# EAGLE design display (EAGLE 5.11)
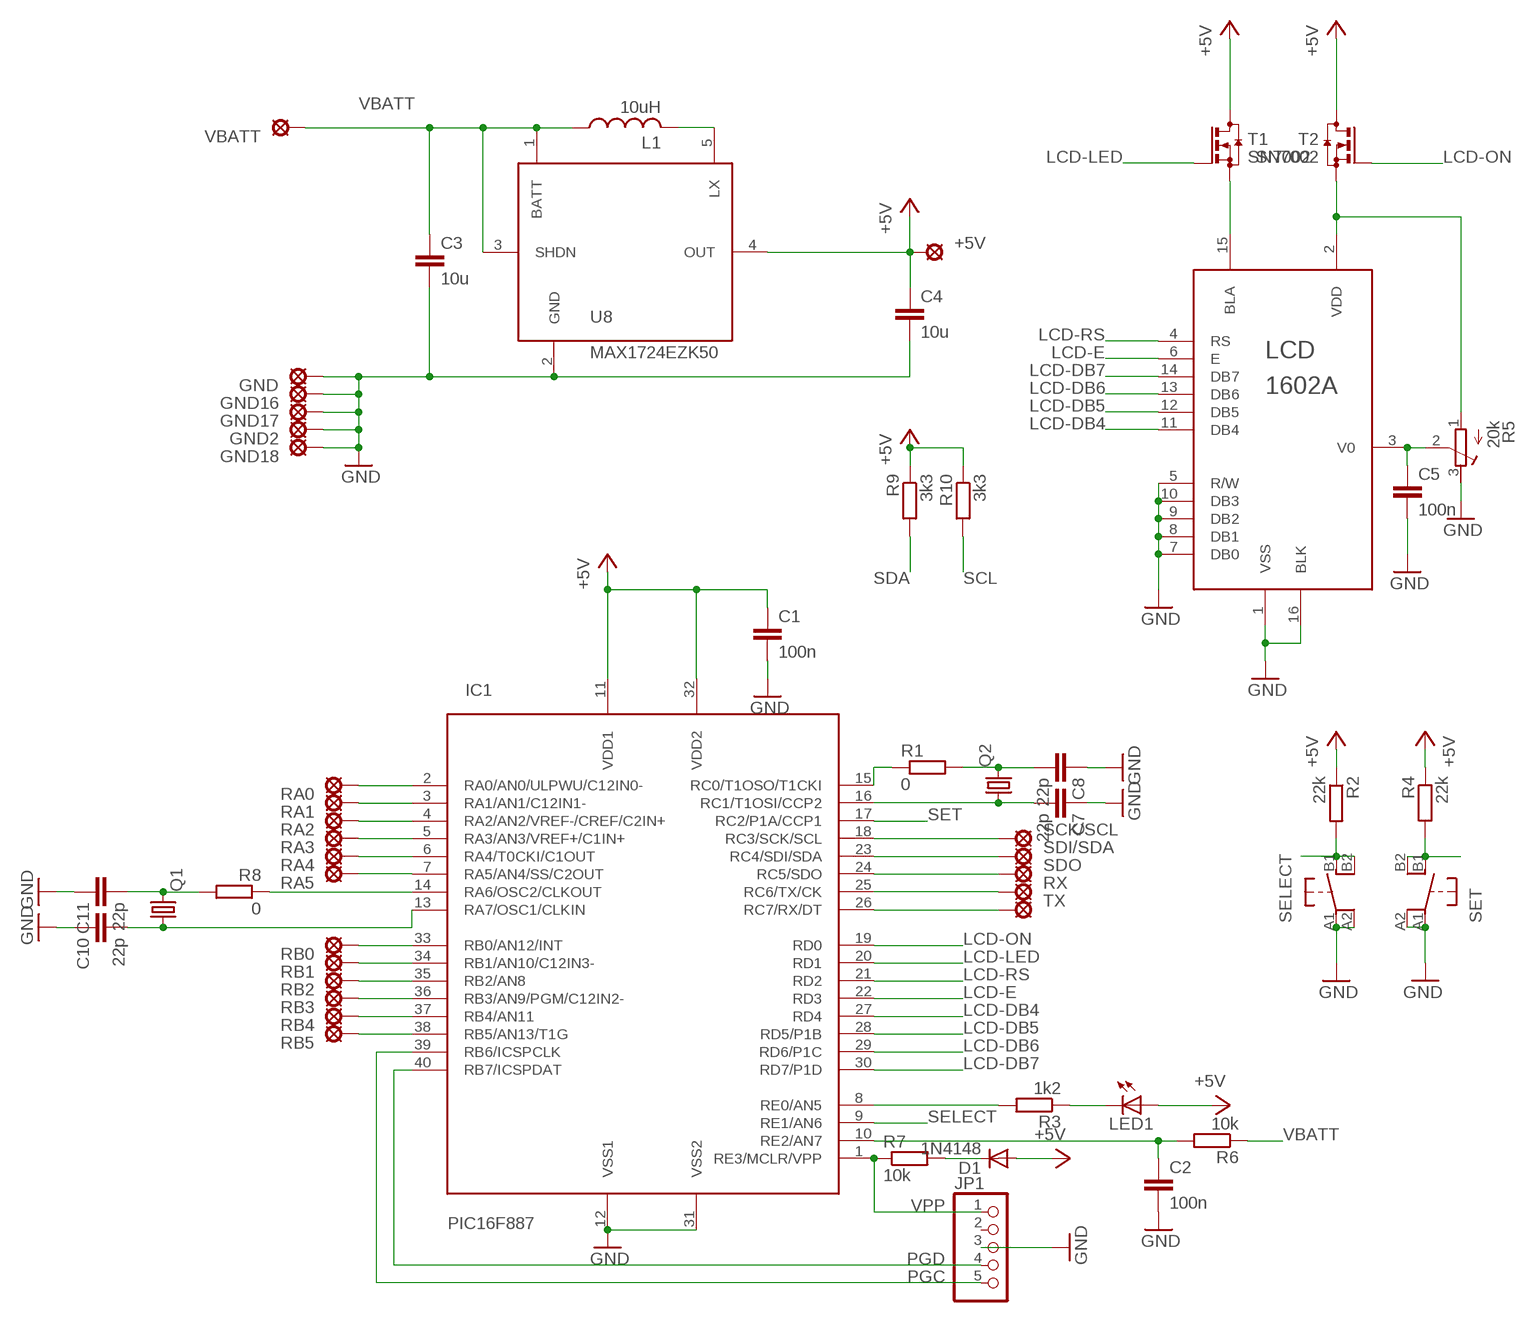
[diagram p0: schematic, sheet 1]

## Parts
+5V  LSP10  [LSP10]
C1  100n  C-EUC0805  [C0805]
C2  100n  C-EUC0805  [C0805]
C3  10u  C-EUC1210  [C1210]
C4  10u  C-EUC1210  [C1210]
C5  100n  C-EUC0805  [C0805]
C7  22p  C-EUC0805  [C0805]
C8  22p  C-EUC0805  [C0805]
C10  22p  C-EUC0805  [C0805]
C11  22p  C-EUC0805  [C0805]
D1  1N4148  1N4148DO35-7  [DO35-7]
GND  LSP10  [LSP10]
GND2  LSP10  [LSP10]
GND16  LSP10  [LSP10]
GND17  LSP10  [LSP10]
GND18  LSP10  [LSP10]
IC1  PIC16F887  [DIL40]
JP1  PINHD-1X5  [1X05]
L1  10uH  COIL-BOURNS  [COIL_BURNS]
LCD  1602A  [1602A]
LED1  LED5MM  [LED5MM]
Q1  CRYSTALSM49  [SM49]
Q2  CRYSTALSM49  [SM49]
R1  0  R-EU_M0805  [M0805]
R2  22k  R-EU_M0805  [M0805]
R3  1k2  R-EU_M0805  [M0805]
R4  22k  R-EU_M0805  [M0805]
R5  20k  R-TRIMM3339P  [RTRIM3339P]
R6  10k  R-EU_M0805  [M0805]
R7  10k  R-EU_M0805  [M0805]
R8  0  R-EU_M0805  [M0805]
R9  3k3  R-EU_M0805  [M0805]
R10  3k3  R-EU_M0805  [M0805]
RA0  LSP10  [LSP10]
RA1  LSP10  [LSP10]
RA2  LSP10  [LSP10]
RA3  LSP10  [LSP10]
RA4  LSP10  [LSP10]
RA5  LSP10  [LSP10]
RB0  LSP10  [LSP10]
RB1  LSP10  [LSP10]
RB2  LSP10  [LSP10]
RB3  LSP10  [LSP10]
RB4  LSP10  [LSP10]
RB5  LSP10  [LSP10]
RX  LSP10  [LSP10]
SCK/SCL  LSP10  [LSP10]
SDI/SDA  LSP10  [LSP10]
SDO  LSP10  [LSP10]
SELECT  PUSHBUTTON  [PUSHBUTTON]
SET  PUSHBUTTON  [PUSHBUTTON]
T1  SN7002  BSS123  [SOT23]
T2  SN7002  BSS123  [SOT23]
TX  LSP10  [LSP10]
U8  MAX1724EZK50  MAX1724  [SOT23-5L]
VBATT  LSP10  [LSP10]

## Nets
+5V: +5V.MP C1.1 C4.1 D1.A IC1.11(VDD1) IC1.32(VDD2) LED1.A R2.1 R4.1 R9.1 R10.1 T1.3(D) T2.3(D) U8.4(OUT)
GND: C1.2 C2.2 C3.2 C4.2 C5.2 C7.1 C8.1 C10.1 C11.1 GND2.MP GND16.MP GND17.MP GND18.MP GND.MP IC1.12(VSS1) IC1.31(VSS2) JP1.3 LCD.1(VSS) LCD.5(R/W) LCD.7(DB0) LCD.8(DB1) LCD.9(DB2) LCD.10(DB3) LCD.16(BLK) R5.3(A) SELECT.A1(P) SELECT.A2(P1) SET.A1(P) SET.A2(P1) U8.2(GND)
LCD-DB4: IC1.27(RD4) LCD.11(DB4)
LCD-DB5: IC1.28(RD5/P1B) LCD.12(DB5)
LCD-DB6: IC1.29(RD6/P1C) LCD.13(DB6)
LCD-DB7: IC1.30(RD7/P1D) LCD.14(DB7)
LCD-E: IC1.22(RD3) LCD.6(E)
LCD-LED: IC1.20(RD1) T1.1(G)
LCD-ON: IC1.19(RD0) T2.1(G)
LCD-RS: IC1.21(RD2) LCD.4(RS)
N$1: LCD.15(BLA) T1.2(S)
N$2: LCD.2(VDD) R5.1(E) T2.2(S)
N$3: C7.2 IC1.16(RC1/T1OSI/CCP2) Q2.1
N$4: C8.2 Q2.2 R1.2
N$5: C5.1 LCD.3(V0) R5.2(S)
N$6: LED1.K(C) R3.1
N$7: IC1.15(RC0/T1OSO/T1CKI) R1.1
N$8: C2.1 IC1.10(RE2/AN7) R6.2
N$9: D1.C R7.2
N$10: IC1.7(RA5/AN4/SS/C2OUT) RA5.MP
N$11: C10.2 IC1.13(RA7/OSC1/CLKIN) Q1.1
N$12: L1.P$2 U8.5(LX)
N$13: IC1.8(RE0/AN5) R3.2
N$16: IC1.24(RC5/SDO) SDO.MP
N$17: C11.2 Q1.2 R8.2
N$18: IC1.14(RA6/OSC2/CLKOUT) R8.1
N$19: IC1.25(RC6/TX/CK) RX.MP
N$20: IC1.26(RC7/RX/DT) TX.MP
N$21: IC1.2(RA0/AN0/ULPWU/C12IN0-) RA0.MP
N$22: IC1.3(RA1/AN1/C12IN1-) RA1.MP
N$23: IC1.4(RA2/AN2/VREF-/CREF/C2IN+) RA2.MP
N$24: IC1.5(RA3/AN3/VREF+/C1IN+) RA3.MP
N$25: IC1.6(RA4/T0CKI/C1OUT) RA4.MP
N$26: IC1.33(RB0/AN12/INT) RB0.MP
N$27: IC1.34(RB1/AN10/C12IN3-) RB1.MP
N$28: IC1.35(RB2/AN8) RB2.MP
N$29: IC1.36(RB3/AN9/PGM/C12IN2-) RB3.MP
N$30: IC1.37(RB4/AN11) RB4.MP
N$31: IC1.38(RB5/AN13/T1G) RB5.MP
PGC: IC1.39(RB6/ICSPCLK) JP1.5
PGD: IC1.40(RB7/ICSPDAT) JP1.4
SCL: IC1.18(RC3/SCK/SCL) R10.2 SCK/SCL.MP
SDA: IC1.23(RC4/SDI/SDA) R9.2 SDI/SDA.MP
SELECT: IC1.9(RE1/AN6) R2.2 SELECT.B1(S) SELECT.B2(S1)
SET: IC1.17(RC2/P1A/CCP1) R4.2 SET.B1(S) SET.B2(S1)
VBATT: C3.1 L1.P$1 R6.1 U8.1(BATT) U8.3(SHDN) VBATT.MP
VPP: IC1.1(RE3/MCLR/VPP) JP1.1 R7.1
Unconnected: JP1.2

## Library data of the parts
+5V GND GND2 GND16-GND18 RA0 RA1-RA5 RB0 RB1-RB5 RX SCK/SCL SDI/SDA SDO TX VBATT = solpad:LSP10: SOLDER PAD
C1-C5 C7 C8 C10 C11 = rcl:C-EU: CAPACITOR, European symbol
D1 = diode:1N4148: DIODE
IC1 = pic16f887:PIC16F887
JP1 = pinhead:PINHD-1X5: PIN HEADER
L1 = powersupply:COIL-BOURNS
LCD = 1602A:1602A
LED1 = led:LED: LED
Q1 Q2 = crystal:CRYSTAL: CRYSTAL; OC_FARNELL: unknown; OC_NEWARK: unknown
R1-R4 R6-R10 = rcl:R-EU_: RESISTOR, European symbol
R5 = rcl:R-TRIMM: Trimm resistor
SELECT SET = cartridge:PUSHBUTTON
T1 T2 = transistor-small-signal:BSS123: N-CHANNEL MOS FET
U8 = powersupply:MAX1724

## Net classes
0 default: width 0.254 mm, clearance 0.203 mm

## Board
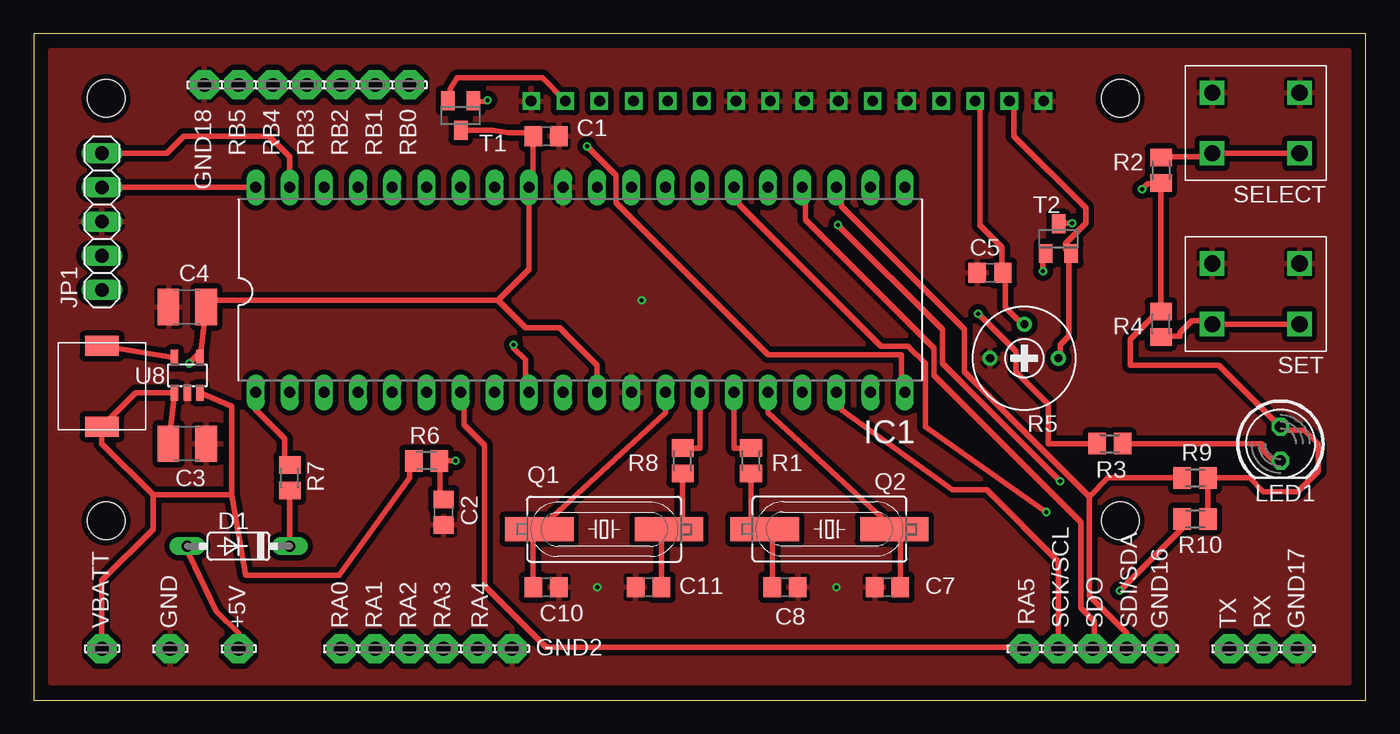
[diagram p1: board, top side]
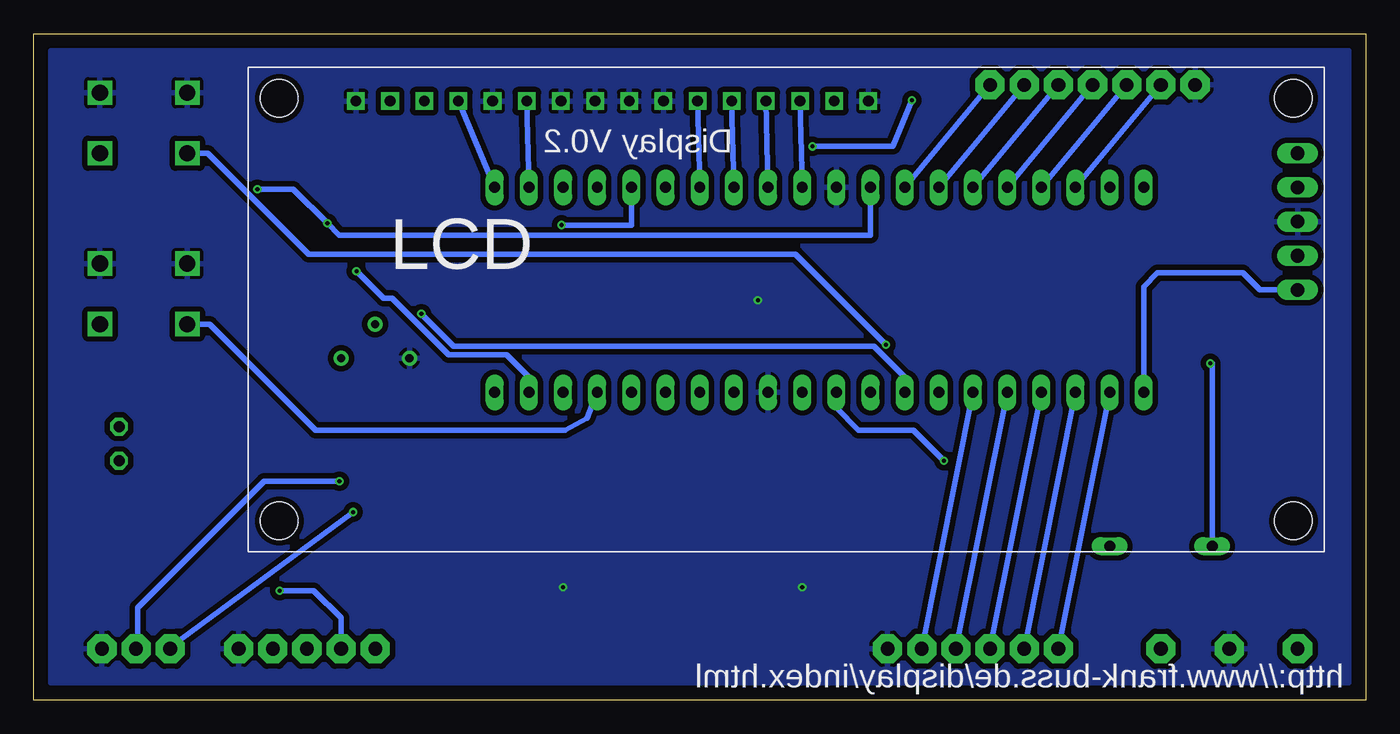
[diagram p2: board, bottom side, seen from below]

Size 99.06 x 49.53 mm. Coordinates in mm from the lower left corner, seen from the top.
Outline: 0,0 99.06,0 99.06,49.53 0,49.53 0,0
Copper layers (1*16): Top 0.035mm / dielectric 1.5mm / Bottom 0.035mm
Design rules "ITead_rule *": minimum track width 16mil, minimum drill 12mil, track to track 6mil, track to pad 6mil, pad to pad 6mil, via to via 6mil, smd to smd 0mil, copper to edge 10mil, drill to drill 10mil, minimum pad ring 10mil, minimum via ring 6mil, stop-mask expansion 2mil, vias tented up to drill 100mil, thermal gap 10mil

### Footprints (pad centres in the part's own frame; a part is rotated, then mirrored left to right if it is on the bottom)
LSP10 = drill 1.016 pad 2.159 octagon: MP 0,0
C0805 = smd 1.3 x 1.5: 1 -0.95,0; 2 0.95,0
C1210 = smd 1.6 x 2.7: 1 -1.4,0; 2 1.4,0
DO35-7 = drill 0.813 long: A 3.81,0; C -3.81,0
DIL40 = drill 0.813 long: 1 -24.13,-7.62; 2 -21.59,-7.62; 3 -19.05,-7.62; 4 -16.51,-7.62; 5 -13.97,-7.62; 6 -11.43,-7.62; 7 -8.89,-7.62; 8 -6.35,-7.62; 9 -3.81,-7.62; 10 -1.27,-7.62; 11 1.27,-7.62; 12 3.81,-7.62; 13 6.35,-7.62; 14 8.89,-7.62; 15 11.43,-7.62; 16 13.97,-7.62; 17 16.51,-7.62; 18 19.05,-7.62; 19 21.59,-7.62; 20 24.13,-7.62; 21 24.13,7.62; 22 21.59,7.62; 23 19.05,7.62; 24 16.51,7.62; 25 13.97,7.62; 26 11.43,7.62; 27 8.89,7.62; 28 6.35,7.62; 29 3.81,7.62; 30 1.27,7.62; 31 -1.27,7.62; 32 -3.81,7.62; 33 -6.35,7.62; 34 -8.89,7.62; 35 -11.43,7.62; 36 -13.97,7.62; 37 -16.51,7.62; 38 -19.05,7.62; 39 -21.59,7.62; 40 -24.13,7.62
1X05 = drill 1.016 long: 1 -5.08,0; 2 -2.54,0; 3 0,0; 4 2.54,0; 5 5.08,0
COIL_BURNS = smd 1.5 x 2.5: P$1 0,0; P$2 6,0
1602A = drill 0.8 square: 1 -31.15,14.29; 2 -28.61,14.29; 3 -26.07,14.29; 4 -23.53,14.29; 5 -20.99,14.29; 6 -18.45,14.29; 7 -15.91,14.29; 8 -13.37,14.29; 9 -10.83,14.29; 10 -8.29,14.29; 11 -5.75,14.29; 12 -3.21,14.29; 13 -0.67,14.29; 14 1.87,14.29; 15 4.41,14.29; 16 6.95,14.29 | hole 2.8: -36.85,14.49; 38.55,14.49; 38.55,-16.91; -36.85,-16.91
LED5MM = drill 0.813 octagon: A -1.27,0; K 1.27,0
SM49 = smd 5.08 x 1.778: 1 -4.826,0; 2 4.826,0
M0805 = smd 1.3 x 1.6: 1 -0.95,0; 2 0.95,0
RTRIM3339P = drill 0.61 round: 1 -2.54,0; 2 0,-2.54; 3 2.54,0
PUSHBUTTON = drill 1.2 square: A1 0,4.5; A2 6.5,4.5; B1 0,0; B2 6.5,0
SOT23 = smd 1 x 1.4: 1 -0.95,-1.1; 2 0.95,-1.1; 3 0,1.1
SOT23-5L = smd 0.55 x 1.2: 1 -0.95,-1.3; 2 0,-1.3; 3 0.95,-1.3; 4 0.95,1.3; 5 -0.95,1.3

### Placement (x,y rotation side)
+5V  15.24,3.81 0 top
C1  38.1,41.91 0 top
C2  30.48,13.97 270 top
C3  11.43,19.05 0 top
C4  11.43,29.21 180 top
C5  71.12,31.75 180 top
C7  63.5,8.38 0 top
C8  55.88,8.38 180 top
C10  38.1,8.38 180 top
C11  45.72,8.38 0 top
D1  15.24,11.43 180 top
GND  10.16,3.81 0 top
GND2  35.56,3.81 0 top
GND16  83.82,3.81 0 top
GND17  93.98,3.81 0 top
GND18  12.7,45.72 0 top
IC1  40.64,30.48 0 top
JP1  5.08,35.56 90 top
L1  5.08,20.32 90 top
LCD  43.94,30.23 0 bottom
LED1  92.71,19.05 270 top
Q1  42.42,12.7 0 top
Q2  59.18,12.7 180 top
R1  53.34,17.78 270 top
R2  83.82,39.37 90 top
R3  80.01,19.05 180 top
R4  83.82,27.94 270 top
R5  73.66,25.4 180 top
R6  29.21,17.78 0 top
R7  19.05,16.51 270 top
R8  48.26,17.78 270 top
R9  86.36,16.51 180 top
R10  86.36,13.46 180 top
RA0  22.86,3.81 0 top
RA1  25.4,3.81 0 top
RA2  27.94,3.81 0 top
RA3  30.48,3.81 0 top
RA4  33.02,3.81 0 top
RA5  73.66,3.81 0 top
RB0  27.94,45.72 0 top
RB1  25.4,45.72 0 top
RB2  22.86,45.72 0 top
RB3  20.32,45.72 0 top
RB4  17.78,45.72 0 top
RB5  15.24,45.72 0 top
RX  91.44,3.81 0 top
SCK/SCL  76.2,3.81 0 top
SDI/SDA  81.28,3.81 0 top
SDO  78.74,3.81 0 top
SELECT  87.63,40.64 0 top
SET  87.63,27.94 0 top
T1  31.75,43.45 180 top
T2  76.2,34.29 0 top
TX  88.9,3.81 0 top
U8  11.43,24.13 0 top
VBATT  5.08,3.81 0 top

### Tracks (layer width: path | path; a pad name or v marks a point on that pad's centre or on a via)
+5V  (via drill 0.3)
  Top 0.406: 34.54,29.72 13.34,29.72 C4.1 U8.4 12.32,25.78 v11.56,25.02 | 34.54,29.72 36.83,32 IC1.32 37.15,38.42 C1.1 36.9,42.16 35.31,42.16 34.12,42.35 T1.3 | 34.54,29.72 36.58,27.69 39.12,27.69 41.91,24.89 IC1.11 | D1.A 11.56,10.79 13.59,6.6 15.24,4.95 +5V.MP | v77.22,35.43 76.2,35.43 T2.3 | v82.42,37.97 82.8,38.35 83.82,38.35 R2.1 R4.1 83.69,28.96 81.53,26.8 81.53,24.89 88.14,24.89 LED1.A 92.96,20.07 94.49,20.07 95.5,19.05 95.5,17.02 93.98,15.49 91.44,15.49 90.42,16.51 R9.1 R10.1
  Bottom 0.406: D1.A 11.43,25.02 v11.56,25.02 | v82.42,37.97 79.76,37.97 v77.22,35.43 76.33,34.54 36.83,34.54 IC1.32
GND  (via drill 0.3)
  other vias: 45.21,29.72 41.91,8.38 59.69,8.38
  pour Top (isolate 0.406): 1.27,48.26 97.79,48.26 97.79,1.27 1.27,1.27
  pour Bottom (isolate 0.406): 1.27,48.26 97.79,48.26 97.79,1.27 1.27,1.27
LCD-DB4
  Bottom 0.406: IC1.27 LCD.11
LCD-DB5
  Bottom 0.406: IC1.28 LCD.12
LCD-DB6
  Bottom 0.406: IC1.29 LCD.13
LCD-DB7
  Bottom 0.406: IC1.30 LCD.14
LCD-E
  Bottom 0.406: IC1.22 LCD.6
LCD-LED  (via drill 0.3)
  Top 0.406: v33.75,44.58 33.64,44.47 T1.1 | v41.15,41.15 43.31,38.99 43.31,36.96 54.61,25.65 64.52,25.65 64.52,23.11 IC1.20
  Bottom 0.406: v33.75,44.58 35.18,41.15 v41.15,41.15
LCD-ON  (via drill 0.3)
  Top 0.406: v75.06,31.88 75.06,33.02 75.18,33.15 T2.1
  Bottom 0.406: v75.06,31.88 73.03,29.84 72.39,29.84 68.2,25.65 63.88,25.65 62.23,24 IC1.19
LCD-RS
  Bottom 0.406: IC1.21 LCD.4
N$1
  Top 0.406: T1.2 30.99,45.48 30.99,45.47 31.5,46.24 37.83,46.24 39.53,44.54 LCD.15
N$2
  Top 0.406: R5.1 76.33,25.53 76.33,26.42 76.96,27.05 76.96,33.02 77.09,33.15 T2.2 76.96,33.27 76.71,33.53 76.71,33.91 78.23,35.43 78.23,36.58 72.9,41.91 72.9,44.2 72.64,44.45 LCD.2
N$3
  Top 0.406: C7.2 64.45,12.7 Q2.1 54.61,21.34 IC1.16
N$4
  Top 0.406: R1.2 53.34,12.7 Q2.2 54.93,12.7 C8.2
N$5
  Top 0.406: R5.2 73.53,27.94 72.26,29.21 72.26,31.62 72.14,31.75 C5.1 72.01,31.88 72.01,33.66 70.36,35.31 70.36,44.2 70.1,44.45 LCD.3
N$6
  Top 0.406: LED1.K 92.2,17.78 91.31,18.67 91.31,19.05 R3.1
N$7
  Top 0.406: R1.1 52.07,18.73 IC1.15
N$8  (via drill 0.3)
  Top 0.406: C2.1 30.48,14.99 30.23,15.24 30.23,17.78 R6.2 v31.37,17.78
  Bottom 0.406: v31.37,17.78 33.66,20.07 37.72,20.07 39.37,21.72 IC1.10
N$9
  Top 0.406: D1.C R7.2
N$10
  Top 0.406: IC1.7 32,22.61 32,20.45 33.53,18.92 33.53,8.51 38.1,3.94 73.66,3.94 RA5.MP
N$11
  Top 0.406: C10.2 37.15,12.7 Q1.1 46.99,21.34 IC1.13
N$12
  Top 0.406: L1.P$2 U8.5
N$13  (via drill 0.3)
  Top 0.406: v70.23,28.7 73.03,25.91 73.03,24.38 75.44,21.97 75.44,19.05 R3.2
  Bottom 0.406: v70.23,28.7 67.82,26.29 36.58,26.29 34.29,24 IC1.8
N$16
  Top 0.406: IC1.24 57.4,37.85 57.4,35.69 66.93,26.16 66.93,24.13 77.85,13.21 77.85,6.86 78.87,5.84 78.87,3.94 SDO.MP
N$17
  Top 0.406: R8.2 48.26,12.7 Q1.2 46.67,12.7 C11.2
N$18
  Top 0.406: R8.1 49.53,18.73 IC1.14
N$19  (via drill 0.3)
  Top 0.406: v59.82,35.31 67.56,27.56 67.56,25.02 v76.33,16.26
  Bottom 0.406: IC1.25 54.61,35.31 v59.82,35.31 | v76.33,16.26 81.92,16.26 91.31,6.86 91.31,3.81 RX.MP
N$20  (via drill 0.3)
  Top 0.406: IC1.26 52.45,37.72 52.45,36.83 62.99,26.29 65.02,26.29 66.29,25.02 66.29,20.32 v75.31,13.97
  Bottom 0.406: v75.31,13.97 88.9,3.94 88.77,4.06 TX.MP
N$21
  Bottom 0.406: RA0.MP IC1.2
N$22
  Bottom 0.406: RA1.MP IC1.3
N$23
  Bottom 0.406: RA2.MP IC1.4
N$24
  Bottom 0.406: RA3.MP IC1.5
N$25
  Bottom 0.406: RA4.MP IC1.6
N$26
  Bottom 0.406: IC1.33 RB0.MP
N$27
  Bottom 0.406: IC1.34 RB1.MP
N$28
  Bottom 0.406: IC1.35 RB2.MP
N$29
  Bottom 0.406: IC1.36 RB3.MP
N$30
  Bottom 0.406: IC1.37 RB4.MP
N$31
  Bottom 0.406: IC1.38 RB5.MP
PGC
  Top 0.406: JP1.5 9.91,40.64 11.18,41.91 17.53,41.91 19.05,40.39 IC1.39
PGD
  Top 0.406: JP1.4 IC1.40
SCL  (via drill 0.3)
  Top 0.406: IC1.18 60.07,22.48 60.07,21.59 68.33,15.62 70.87,15.62 76.2,10.29 SCK/SCL.MP | R10.2 85.41,12.77 v80.77,8.13
  Bottom 0.406: v80.77,8.13 78.23,8.13 76.2,6.1 SCK/SCL.MP
SDA
  Top 0.406: IC1.23 60.07,37.72 60.07,36.7 69.22,27.56 69.22,24.38 78.49,15.11 | 78.49,15.11 78.49,7.75 81.28,4.95 SDI/SDA.MP | R9.2 79.88,16.51 78.49,15.11
SELECT  (via drill 0.3)
  Top 0.406: R2.2 83.82,40.39 87.63,40.39 SELECT.B1 SELECT.B2 | IC1.9 36.58,23.11 36.58,25.27 35.69,26.16 v35.69,26.42
  Bottom 0.406: v35.69,26.42 42.42,33.15 78.61,33.15 86.11,40.64 SELECT.B1
SET
  Top 0.406: R4.2 83.82,27.05 85.22,27.05 85.22,27.3 86.11,28.19 87.63,28.19 SET.B1 SET.B2
  Bottom 0.406: IC1.17 57.91,20.95 59.56,20.07 78.11,20.07 85.98,27.94 SET.B1
VBATT
  Top 0.406: VBATT.MP 5.08,8.89 8.89,12.7 8.89,15.24 | 8.89,15.24 5.08,19.05 L1.P$1 7.59,22.83 U8.1 C3.1 | U8.3 14.73,21.84 14.73,15.24 | 8.89,15.24 14.73,15.24 | R6.1 28.19,17.78 27.94,17.53 27.94,16.51 22.73,9.27 15.75,9.27 14.73,15.24
VPP
  Top 0.406: IC1.1 16.51,21.59 18.67,19.43 18.67,17.91 19.05,17.53 R7.1
  Bottom 0.406: JP1.1 7.87,30.48 9.14,31.75 15.49,31.75 16.51,30.73 IC1.1

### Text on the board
bPlace: Display V0.2 | http://www.frank-buss.de/display/index.html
